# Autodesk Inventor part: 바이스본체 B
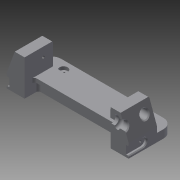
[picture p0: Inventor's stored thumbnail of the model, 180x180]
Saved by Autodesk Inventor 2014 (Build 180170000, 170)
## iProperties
Created: 2017-04
Part Number: 바이스본체 B
Material: 일반
Document SubType Name: Modeling
Designer: mduedu
Density: 1 g/cm^3
Appearance: 기본값
Author: mduedu
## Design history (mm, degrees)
sketch "스케치1"
  geometry: L1 (-75, 0)-(75, 0); L2 (-75, 0)-(-75, 17); L3 (-53, 17)-(53, 17); L4 (75, 17)-(75, 0); L5 (-75, 17)-(-65.173, 44); L6 (-65.173, 44)-(-53, 44); L7 (-53, 44)-(-53, 17); L8 (0, 0)-(0, 17); L9 (75, 17)-(65.173, 44); L10 (65.173, 44)-(53, 44); L11 (53, 44)-(53, 17); 1 further point
  constraints: 22 end point, 4 perpendicular, 2 horizontal alignment, 2 midpoint, 2 symmetric about line, 1 coincident, 1 collinear, 1 horizontal, 1 vertical
  dimensions: "d0" = 150 distance of L1.start L1.end; "d1" = 17 distance of L1.start L2.end; "d2" = 27 distance of L3.start L6.end; "d3" = 22 distance of L3.start L2.end; "d4" = 70 deg angle of L3 L5; "d54" = 20 deg angle of L9 L4
extrude "돌출1" new body sketch "스케치1" stored distance "d5" = 70; taper "d6" = 0 deg
sketch "스케치2"
  geometry: L1 (0, 70)-(106, 70) reference; L2 (106, 70)-(106, 0) reference; L3 (106, 0)-(0, 0) reference; L4 (0, 47)-(106, 47); L5 (106, 47)-(106, 23); L6 (106, 23)-(0, 23); L7 (0, 23)-(0, 47); L8 (0, 70)-(0, 0) reference; 2 further points
  constraints: 8 end point, 2 parallel, 2 point on line, 1 horizontal, 1 horizontal alignment, 1 midpoint, 1 perpendicular
  dimensions: "d7" = 24 distance between parallel lines of L6 L4
extrude "돌출2" cut sketch "스케치2" stored distance "d9" = 70; taper "d10" = 0 deg
sketch "스케치3"
  geometry: L1 (22, -23)-(128, -23) reference; L2 (128, -47)-(22, -47) reference; L3 (22, -18)-(128, -18); L4 (128, -52)-(22, -52); L5 (22, -18)-(22, -52); L6 (128, -18)-(128, -52); 1 further point
  constraints: 8 end point, 3 parallel, 2 point on line, 1 perpendicular
  dimensions: "d11" = 5 distance between parallel lines of L3 L1; "d12" = 5 distance between parallel lines of L4 L2
extrude "돌출3" cut sketch "스케치3" distance "d13" = 12; taper "d14" = 0 deg
fillet "모깎기1" dims "d15" = 3, "d16" = 3
sketch "스케치4"
  geometry: L1 (103, 23)-(3, 23) reference; L2 (0, 26)-(0, 0) reference; L3 (106, 0)-(0, 0) reference; L4 (106, 26)-(106, 0) reference; L5 (96, 0)-(90, 0); L6 (90, 0)-(90, 19.5); L7 (96, 19.5)-(96, 0); L8 (90, 19.5)-(96, 19.5); A1 r 3 centre (3, 26) between (0, 26) and (3, 23) reference; A2 r 3 centre (103, 26) between (103, 23) and (106, 26) reference; 1 further point
  constraints: 8 end point, 2 perpendicular, 1 horizontal, 1 parallel, 1 point on line
  dimensions: "d17" = 10 distance between parallel lines of L7 L4; "d18" = 6 distance between parallel lines of L7 L6; "d27" = 3.5 distance between parallel lines of L8 L1
extrude "돌출4" join sketch "스케치4" distance "d19" = 12; taper "d20" = 0 deg
chamfer "모따기1" distance "d21" = 3; stored, may be unused: second distance "d22" = 2, angle "d23" = 45 deg
chamfer "모따기2" distance "d24" = 3; stored, may be unused: second distance "d25" = 2, angle "d26" = 45 deg
sketch "스케치5"
  geometry: L1 (-15.5, 35.8)-(-15.5, -25.8) reference; L2 (19.5, 0)-(0, 0) reference; C1 r 6.5 at (9.5, 15); 1 further point
  constraints: 1 centre point
  dimensions: "d28" = 13 diameter of C1; "d30" = 15 distance from line of C1.centre L2; "d31" = 25 distance from line of C1.centre L1
extrude "돌출5" cut sketch "스케치5" stored distance "d32" = 12; taper "d33" = 0 deg
sketch "스케치6"
  geometry: C1 r 5 at (-10, 15); C2 r 5 at (-60, 15); A1 r 6.5 centre (-10, 15) between (-15.766, 12) and (-4.234, 12) reference; A2 r 6.5 centre (-60, 15) between (-65.766, 12) and (-54.234, 12) reference; 1 further point
  constraints: 2 centre point, 2 coincident
  dimensions: "d34" = 10 diameter of C1; "d35" = 10 diameter of C2 (= d34)
extrude "돌출6" cut sketch "스케치6" stored distance "d36" = 12; taper "d37" = 0 deg
chamfer "모따기3" distance "d38" = 1; stored, may be unused: second distance "d39" = 2, angle "d40" = 45 deg
chamfer "모따기4" distance "d41" = 1; stored, may be unused: second distance "d42" = 2, angle "d43" = 45 deg
sketch "스케치7"
  geometry: L1 (-35, 35.8)-(-35, -25.8) reference; L2 (-70, 0)-(0, 0) reference; C1 r 5 at (-35, 15); 1 further point
  constraints: 1 centre point, 1 point on line
  dimensions: "d44" = 10 diameter of C1; "d45" = 15 distance from line of C1.centre L2
extrude "돌출7" cut sketch "스케치7" stored distance "d46" = 12; taper "d47" = 0 deg
chamfer "모따기5" distance "d48" = 1; stored, may be unused: second distance "d49" = 2, angle "d50" = 45 deg
node "작업축1"
sketch "스케치8"
  geometry: L1 (-105, 32)-(105, 32) reference; L2 (58, 32)-(64, 32); L3 (64, 32)-(64, 40); L4 (64, 40)-(58, 40); L5 (58, 40)-(58, 32); L6 (53, 38)-(53, 26) reference; 1 further point
  constraints: 8 end point, 2 parallel, 1 horizontal, 1 perpendicular, 1 point on line
  dimensions: "d51" = 5 distance from line of L6 L2.start; "d52" = 6 distance of L3.end L4.end; "d53" = 16 diameter of L4 L1
revolve "회전1" sketch "스케치8" stored, may be unused: angle "d55" = 90 deg
fillet "모깎기2"
chamfer "모따기6" distance "d56" = 1; stored, may be unused: second distance "d57" = 2, angle "d58" = 45 deg
sketch "스케치9"
  geometry: L1 (17.5, 3)-(52.5, 3); L2 (52.5, 13)-(17.5, 13); L3 (70, 0)-(0, 0) reference; L4 (17.5, 8)-(52.5, 8); A1 r 5 centre (17.5, 8) between (17.5, 13) and (17.5, 3); A2 r 5 centre (52.5, 8) between (52.5, 3) and (52.5, 13); 3 further points
  constraints: 6 end point, 4 point on circle, 3 tangent, 2 centre point, 2 midpoint, 2 parallel, 1 horizontal, 1 vertical alignment
  dimensions: "d59" = 35 distance of L4.start L4.end; "d61" = 5 radius of A2; "d62" = 8 distance between parallel lines of L3 L4
extrude "돌출8" cut sketch "스케치9" distance "d63" = 3; taper "d64" = 0 deg
chamfer "모따기7" distance "d65" = 1; stored, may be unused: second distance "d66" = 2, angle "d67" = 45 deg
chamfer "모따기8" distance "d68" = 1; stored, may be unused: second distance "d69" = 2, angle "d70" = 45 deg
feature "분할1"
sketch "스케치10"
  geometry: A1 r 5 centre (0, 0) between (0, 5) and (0, -5) reference; 1 further point
  constraints: 1 coincident
hole "구멍1" sketch "스케치10" at (0, 0) diameter "d71" = 2.459; stored, may be unused: countersink angle "d75" = 90 deg, drill point angle "d77" = 120 deg; dims "d72" = 4.5, "d73" = 4, "d74" = 2, "d76" = 6
sketch "스케치11"
  geometry: L1 (0, 0)-(0, 27) reference; L2 (0, 27)-(-35, 27) reference; 2 further points
  dimensions: "d78" = 12 distance from line of point (-12, 15.5) L1; "d79" = 11.5 distance from line of point (-12, 15.5) L2
hole "구멍2" sketch "스케치11" at (-12, 15.5) diameter "d80" = 3.242; stored, may be unused: countersink angle "d84" = 90 deg, drill point angle "d86" = 120 deg; dims "d81" = 8, "d82" = 4, "d83" = 2, "d85" = 10
sketch "스케치12"
  geometry: L1 (-75, -35)-(-75, 0) reference; L2 (75, -35)-(75, 0) reference; L3 (75, -35)-(-75, -35); L4 (-75, -35)-(-75, -55); L5 (-75, -55)-(75, -55); L6 (75, -55)-(75, -35); 1 further point
  constraints: 8 end point, 2 parallel, 1 horizontal, 1 perpendicular, 1 point on line
  dimensions: "d87" = 20 distance of L3.end L4.end; "d89" = 150 distance of L4.end L5.end (derived)
extrude "돌출9" join sketch "스케치12" distance "d90" = 10; taper "d91" = 0 deg
sketch "스케치13"
  geometry: L1 (-75, 55)-(-75, 35) reference; L2 (75, 35)-(75, 55) reference; L3 (-75, 45)-(75, 45); 3 further points
  constraints: 2 end point, 2 midpoint, 2 point on line
  dimensions: "d92" = 50 horizontal distance of point (-50, 45) point (0, 0); "d93" = 100 distance of point (50, 45) point (-50, 45)
fillet "모깎기3" dims "d94" = 12
chamfer "모따기9" distance "d95" = 1; stored, may be unused: second distance "d96" = 2, angle "d97" = 45 deg
hole "구멍3" sketch "스케치13" diameter "d98" = 4.134; stored, may be unused: countersink angle "d102" = 90 deg, drill point angle "d104" = 118 deg; dims "d99" = 6, "d100" = 10, "d101" = 4, "d103" = 8
node "솔리드1"
mirror "대칭1"
mirror "대칭2"
mirror "대칭3"
mirror "대칭4"
node "투영된 루프1"
